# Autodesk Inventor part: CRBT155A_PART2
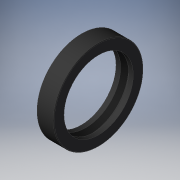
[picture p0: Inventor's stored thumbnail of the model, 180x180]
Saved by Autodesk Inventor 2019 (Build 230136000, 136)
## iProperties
Created: 2023-09
Part Number: CRBT155A_PART2
Material: Generic
Catalog Web Link: www.cadenas.de
Description: -
Vendor: IKO
Document SubType Name: Modeling
Designer: psAdmin
Manufacturer: IKO
Mass: 0.978423 g
Surface Area: 12.1379 cm^2
Volume: 0.978423 cm^3
Density: 1 g/cm^3
Appearance: PSOLRGB-175-175-175
Category: PARTsolutions
Company: IKO
Title: CRBT155A_PART2
Author: Cadenas PARTsolutions
PSOL_IDENT_0: {$CADENAS_DATA/23d-libs/iko/iko_bearings/crossed_rb/ultra_slim_type_crb/ultra_slim_type_crbt.prj},23
PSOL_IDENT_1: 2 {VTYP=3D},{NB=CRBT155A_PART2},{LINA=CRBT155A_PART2},{NN=Ultra Slim Type Crossed Roller Bearings (C
PSOL_IDENT_2: RBT...A)_PART2},{NOPRJ=TRUE},{DATE=09.07.2020 23:28:49},{GEOMDATE=08.07.2020 06:24:28},{VERSION=},{L
PSOL_IDENT_3: INEID=220},{WBVAR=},{WBNUMERIC=}  {NB=CRBT155A_PART2},{LINA=CRBT155A_PART2},{KT=DUMMY},{IDNR=},{STDR
PSOL_IDENT_4: T=15},{ORDER=CRBT155A},{MASS=11.9},{SD=15},{D=26},{B=5},{SR=0.15},{SDA=17.5},{DA=22.0},{DAR=2.0},{ZE
PSOL_IDENT_5: FF=16},{RS=0.3},{DETC=1.6},{PCDRL=19.6},{SDOR=20.10},{DIRR=19.10},{COG=0.0},{SDOG=0.0},{OH=0.0},{NH=
PSOL_IDENT_6: 0},{CR=1320},{COR=1110},{SC=0},{N=8},{N1=1.67}
NB: CRBT155A_PART2
NBSYN: $ORDER._PART2
LINA: CRBT155A_PART2
CATALOG: IKO (Nippon Thompson
STDRT: 15
ORDER: CRBT155A
MASS: 11.9
SD: 15
D: 26
B: 5
SR: 0.15
SDA: 17.5
DA: 22
CR: 1320
COR: 1110
SUPPLIER: IKO
ARTICLENO: CRBT155A_PART2
BOMINFO: CRBT155A_PART2
CREATOR: CADENAS GmbH
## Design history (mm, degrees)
sketch "Sketch_1"
  geometry: L1 (5, 0)-(0, 0); L2 (0, 10.05)-(5, 10.05); L3 (5, 10.05)-(5, 12.85); L4 (4.85, 13)-(0.15, 13); L5 (0, 12.85)-(0, 10.05); A1 r 0.15 centre (4.85, 12.85) between (5, 12.85) and (4.85, 13); A2 r 0.15 centre (0.15, 12.85) between (0.15, 13) and (0, 12.85)
  constraints: 10 end point, 4 point on circle, 2 centre point
revolve "Revolution1" sketch "Sketch_1" stored, may be unused: angle "d0" = 360 deg
sketch "Sketch_4"
  geometry: L1 (3.5, 0)-(1.5, 0); L2 (1.086, 9.8)-(2.5, 8.386); L3 (2.5, 8.386)-(3.914, 9.8); L4 (3.914, 9.8)-(2.5, 11.214); L5 (2.5, 11.214)-(1.086, 9.8)
  constraints: 10 end point
revolve "Revolution2" sketch "Sketch_4" stored, may be unused: angle "d1" = 360 deg
body "Solid1"
